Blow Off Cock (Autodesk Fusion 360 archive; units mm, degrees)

design "Blow Off Cock" references "Stud", "Gland", "Cock", "Body", "Nut"
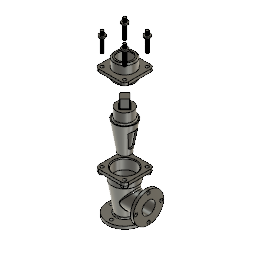
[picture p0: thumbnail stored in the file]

design "Nut"
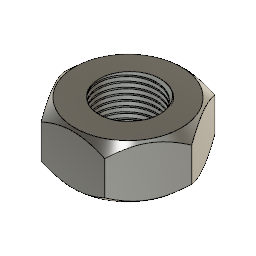
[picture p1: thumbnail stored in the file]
sketch "Sketch1" plane through (0, 0, 0) normal (0, 0, 1) x axis (1, 0, 0)
  line L1 (-12, 0) -> (-6, 10.3923)
  line L2 (-6, -10.3923) -> (-12, 0)
  line L3 (6, -10.3923) -> (-6, -10.3923)
  line L4 (12, 0) -> (6, -10.3923)
  line L5 (6, 10.3923) -> (12, 0)
  line L6 (-6, 10.3923) -> (6, 10.3923)
  circle C1 centre (0, 0) radius 6
  point P1 (0, 0)
  point P2 (0, 0)
  point P9 (0, 0)
  point P4 (-12, 0)
  point P7 (12, 0)
  point P3 (-6, 10.3923)
  point P8 (6, 10.3923)
  coincident P1 P2
  coincident P2 P9
  horizontal P4 P7
  dimension "d1" diameter C1 = 12
  dimension "d2" distance P3 P8 = 12
extrude "Extrude1" new body sketch "Sketch1" distance 10
sketch "Sketch2" plane through (0, 0, 5) normal (0, 0, 1) x axis (-1, 0, 0)
  line L1 (6, -10.3923) -> (-6, -10.3923)
  line L2 (12, 0) -> (6, -10.3923)
  line L3 (6, 10.3923) -> (12, 0)
  line L4 (-6, 10.3923) -> (6, 10.3923)
  line L5 (-12, 0) -> (-6, 10.3923)
  line L6 (-6, -10.3923) -> (-12, 0)
  circle C1 centre (0, 0) radius 6
  circle C2 centre (0, 0) radius 10
  point P1 (0, 0)
  point P9 (0, 0)
  coincident P1 P9
  dimension "d5" diameter C2 = 20
extrude "Extrude2" sketch "Sketch2" profile of C1 C2 no distance stored taper 48
mirror "Mirror1"
thread "Thread1"

design "Cock"
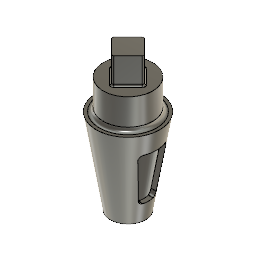
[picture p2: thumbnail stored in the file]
sketch "Sketch1" plane through (0, 0, 0) normal (0, 1, 0) x axis (1, 0, 0)
  line L1 (23, 0) -> (17, 0)
  line L2 (41, -110) -> (23, 0)
  line L3 (0, -144.3099) -> (0, 0)
  line L4 (17, 0) -> (34.0182, -104)
  line L5 (37.7698, 0) -> (0, 0)
  line L6 (32, -110) -> (41, -110)
  line L7 (32, -149) -> (32, -110)
  line L8 (26, -104) -> (34.0182, -104)
  line L9 (26, -143) -> (26, -104)
  line L10 (0, -149) -> (32, -149)
  line L11 (0, -143) -> (26, -143)
  line L12 (0, -143) -> (0, -149)
  point P1 (0, 0)
  point P4 (0, 0)
  point P8 (0, 0)
  point P7 (17, 0)
  point P14 (0, -149)
  point P15 (0, -143)
  point P3 (41, -110)
  horizontal L1
  coincident P1 P4
  perpendicular L1 L3
  parallel L2 L4
  coincident P1 P8
  perpendicular L3 L5
  horizontal P1 P7
  horizontal L6
  perpendicular L6 L7
  horizontal L8
  perpendicular L8 L9
  perpendicular L7 L10
  coincident L3 P14
  coincident L3 P15
  perpendicular L3 L11
  dimension "d1" = 46
  dimension "d2" = 34
  dimension "d3" distance L1 P3 = 110
  dimension "d4" = 82
  dimension "d5" distance L6 L8 = 6
  dimension "d7" = 64
  dimension "d8" distance L7 L9 = 6
  dimension "d9" distance L5 L10 = 149
  dimension "d10" distance L10 L11 = 6
revolve "Revolve1" sketch "Sketch1" AlongAngle 360
sketch "Sketch2" plane through (0, 0, 149) normal (0, 0, 1) x axis (-1, 0, 0)
  line L1 (21.2132, 0) -> (0, -21.2132)
  line L2 (0, 21.2132) -> (21.2132, 0)
  line L3 (-21.2132, 0) -> (0, 21.2132)
  line L4 (0, -21.2132) -> (-21.2132, 0)
  point P1 (0, 0)
  point P3 (21.2132, 0)
  point P5 (-21.2132, 0)
  point P2 (0, -21.2132)
  point P4 (0, 21.2132)
  perpendicular L2 L3
  horizontal P1 P3
  horizontal P1 P5
  vertical P1 P2
  vertical P1 P4
  equal L1 L2
  equal L1 L4
  dimension "d28" distance P2 P5 = 30
extrude "Extrude1" add sketch "Sketch2" along normal blind 34
fillet "Fillet1" radius 2
fillet "Fillet2" radius 2
fillet "Fillet3" radius 5
fillet "Fillet4" radius 5
sketch "Sketch5" plane through (0, 0, 0) normal (1, 0, 0) x axis (0, 1, 0)
  line L1 (-23, 0) -> (23, 0)
  line L2 (0, 97.021) -> (0, 0)
  line L3 (13.3134, 85) -> (-13.3134, 85)
  line L4 (11.5626, 27.3601) -> (18.2723, 79.3601)
  line L5 (-6.6037, 23) -> (6.6037, 23)
  line L6 (-18.2723, 79.3601) -> (-11.5626, 27.3601)
  line L7 (-41, 110) -> (41, 110)
  arc A1 centre (-13.3134, 80) radius 5 clockwise from (-18.2723, 79.3601) to (-13.3134, 85)
  arc A2 centre (13.3134, 80) radius 5 clockwise from (13.3134, 85) to (18.2723, 79.3601)
  arc A3 centre (6.6037, 28) radius 5 clockwise from (11.5626, 27.3601) to (6.6037, 23)
  arc A4 centre (-6.6037, 28) radius 5 clockwise from (-6.6037, 23) to (-11.5626, 27.3601)
  point P1 (0, 0)
  point P4 (0, 0)
  point P6 (-19, 85)
  point P7 (19, 85)
  point P8 (11, 23)
  point P9 (-11, 23)
  coincident P1 P4
  perpendicular L1 L2
  perpendicular L2 L3
  perpendicular L2 L5
  symmetric L2 P6 P7
  symmetric L2 P8 P9
  coincident P6 L6
  tangent L3 A1
  tangent L6 A1
  coincident P7 L4
  coincident P7 L3
  tangent L4 A2
  tangent L3 A2
  equal A1 A2
  coincident P8 L4
  tangent L4 A3
  tangent L5 A3
  equal A1 A3
  coincident P9 L5
  coincident P9 L6
  tangent L5 A4
  tangent L6 A4
  equal A1 A4
  dimension "d36" distance L3 L5 = 62
  dimension "d37" distance L3 L7 = 25
  dimension "d38" distance P6 P7 = 38
  dimension "d39" distance P8 P9 = 22
  dimension "d40" radius A1 = 5
extrude "Extrude4" cut sketch "Sketch5" profile of L3 L4 L5 L6 A1 A2 A3 A4 no distance stored
sketch "Sketch4" plane through (0, 0, 143) normal (0, 0, -1) x axis (1, 0, 0)
  circle C1 centre (0, 0) radius 26
  circle C2 centre (0, 0) radius 12
  point P1 (0, 0)
  point P3 (0, 0)
  coincident P1 P3
  dimension "d31" diameter C2 = 24
extrude "Extrude3" cut sketch "Sketch4" profile of C2 against normal blind 32
fillet "Fillet5" radius 5
fillet "Fillet6" radius 5

design "Gland"
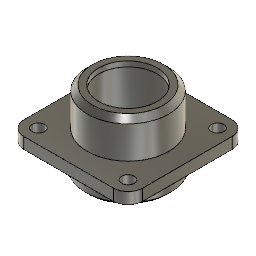
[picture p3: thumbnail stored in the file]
sketch "Sketch1" plane through (0, 0, 0) normal (0, 0, 1) x axis (1, 0, 0)
  circle C1 centre (0, 0) radius 41
  point P1 (0, 0)
  point P2 (0, 0)
  coincident P1 P2
  dimension "d1" diameter C1 = 82
extrude "Extrude1" new body sketch "Sketch1" along normal blind 25
sketch "Sketch2" plane through (0, 0, 25) normal (0, 0, 1) x axis (-1, 0, 0)
  line L1 (57, -57) -> (-57, -57)
  line L2 (57, 57) -> (57, -57)
  line L3 (-57, 57) -> (57, 57)
  line L4 (-57, -57) -> (-57, 57)
  line L5 (57, 57) -> (-57, -57)
  line L6 (-57, 57) -> (57, -57)
  circle C1 centre (0, 0) radius 41
  point P7 (0, 0)
  point P1 (0, 0)
  point P3 (-57, -57)
  point P4 (57, -57)
  point P5 (57, 57)
  horizontal L1
  perpendicular L1 L2
  parallel L1 L3
  parallel L2 L4
  coincident L5 P7
  coincident L6 P7
  coincident P1 P7
  dimension "d4" distance P3 P4 = 114
  dimension "d5" distance P4 P5 = 114
extrude "Extrude2" add sketch "Sketch2" profile of C1 L1 L2 L3 L4 along normal blind 11
fillet "Fillet1" sketch "Sketch5" radius 14
sketch "Sketch3" plane through (0, 0, 36) normal (0, 0, 1) x axis (-1, 0, 0)
  line L1 (43, -57) -> (-43, -57)
  line L2 (57, 43) -> (57, -43)
  line L3 (-43, 57) -> (43, 57)
  line L4 (-57, -43) -> (-57, 43)
  arc A1 centre (-43, -43) radius 14 clockwise from (-43, -57) to (-57, -43)
  arc A2 centre (43, -43) radius 14 clockwise from (57, -43) to (43, -57)
  arc A3 centre (43, 43) radius 14 clockwise from (43, 57) to (57, 43)
  arc A4 centre (-43, 43) radius 14 clockwise from (-57, 43) to (-43, 57)
  circle C1 centre (0, 0) radius 39
  point P1 (0, 0)
  point P14 (0, 0)
  coincident P1 P14
  dimension "d9" diameter C1 = 78
extrude "Extrude3" add sketch "Sketch3" profile of C1 along normal blind 36
chamfer "Chamfer1" distance 5 rotateAngle 45
sketch "Sketch4" plane through (0, 0, 0) normal (0, 1, 0) x axis (1, 0, 0)
  line L1 (-34, -72) -> (34, -72)
  line L2 (0, -90.6958) -> (0, 0)
  line L3 (-28, -72) -> (0, -72)
  line L4 (-28, -67) -> (-28, -72)
  line L5 (39, -67) -> (-39, -67)
  line L6 (-34, -67) -> (-28, -67)
  line L7 (-34, -21) -> (-34, -67)
  line L8 (-32, -21) -> (-34, -21)
  line L9 (41, 0) -> (-41, 0)
  line L10 (-32, 0) -> (-32, -21)
  line L11 (0, 0) -> (-32, 0)
  line L12 (0, -72) -> (0, 0)
  point P1 (0, 0)
  point P4 (0, 0)
  point P6 (0, -72)
  point P11 (-34, -67)
  point P16 (-32, 0)
  point P7 (-28, -72)
  point P17 (0, 0)
  point P18 (0, 0)
  point P8 (-28, -67)
  point P13 (-32, -21)
  coincident P1 P4
  perpendicular L1 L2
  coincident L2 P6
  perpendicular L2 L3
  perpendicular L3 L4
  coincident L5 P11
  perpendicular L4 L6
  perpendicular L5 L7
  perpendicular L7 L8
  coincident L9 P16
  perpendicular L5 L10
  coincident L1 P7
  coincident P1 P17
  coincident P1 P18
  dimension "d15" distance L2 L4 = 28
  dimension "d16" distance L1 P8 = 5
  dimension "d17" distance L2 L7 = 34
  dimension "d18" distance L2 L10 = 32
  dimension "d19" distance P13 P16 = 21
revolve "Revolve1" sketch "Sketch4" AlongAngle 360
sketch "Sketch5" plane through (0, 0, 36) normal (0, 0, 1) x axis (-1, 0, 0)
  line L1 (43, -57) -> (-43, -57)
  line L2 (57, 43) -> (57, -43)
  line L3 (-43, 57) -> (43, 57)
  line L4 (-57, -43) -> (-57, 43)
  circle C1 centre (0, 0) radius 39
  arc A1 centre (-43, -43) radius 14 clockwise from (-43, -57) to (-57, -43)
  arc A2 centre (43, -43) radius 14 clockwise from (57, -43) to (43, -57)
  arc A3 centre (43, 43) radius 14 clockwise from (43, 57) to (57, 43)
  arc A4 centre (-43, 43) radius 14 clockwise from (-57, 43) to (-43, 57)
  circle C2 centre (43, 43) radius 6
  concentric A3 C2
  dimension "d26" diameter C2 = 12
extrude "Extrude4" cut sketch "Sketch5" profile of C2 to an object
rectangular_pattern "R-Pattern1" uSpaceDistance 86 vSpaceDistance 86
chamfer "Chamfer2" distance 3 rotateAngle 45

design "Stud"
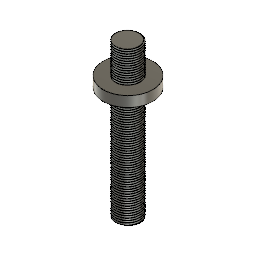
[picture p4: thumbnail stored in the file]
sketch "Sketch1" plane through (0, 0, 0) normal (0, 0, 1) x axis (1, 0, 0)
  circle C1 centre (0, 0) radius 6
  point P1 (0, 0)
  point P2 (0, 0)
  coincident P1 P2
  dimension "d1" diameter C1 = 12
extrude "Extrude1" new body sketch "Sketch1" along normal blind 54
sketch "Sketch2" plane through (0, 0, 54) normal (0, 0, 1) x axis (-1, 0, 0)
  circle C1 centre (0, 0) radius 6
  circle C2 centre (0, 0) radius 12
  point P1 (0, 0)
  point P3 (0, 0)
  coincident P1 P3
  dimension "d4" diameter C2 = 24
extrude "Extrude2" add sketch "Sketch2" along normal blind 5
sketch "Sketch3" plane through (0, 0, 59) normal (0, 0, 1) x axis (-1, 0, 0)
  circle C1 centre (0, 0) radius 12
  circle C2 centre (0, 0) radius 6
  point P1 (0, 0)
  point P3 (0, 0)
  coincident P1 P3
  dimension "d7" diameter C2 = 12
extrude "Extrude3" add sketch "Sketch3" profile of C2 along normal blind 15
thread "Thread1"
thread "Thread2"

design "Body"
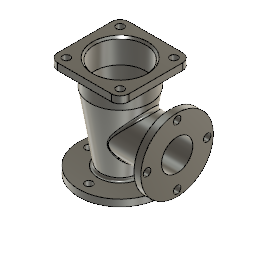
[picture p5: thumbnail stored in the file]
sketch "Sketch1" plane through (0, 0, 0) normal (0, 1, 0) x axis (1, 0, 0)
  line L1 (0, -187.0761) -> (0, 0)
  line L2 (30, -22) -> (30, 0)
  line L3 (17.5, 0) -> (30, 0)
  line L4 (17.5, -33) -> (17.5, 0)
  line L5 (66, -22) -> (30, -22)
  line L6 (66, -33) -> (66, -22)
  line L7 (30, -33) -> (66, -33)
  line L8 (48, -143) -> (30, -33)
  line L9 (48, -171) -> (48, -143)
  line L10 (41, -171) -> (48, -171)
  line L11 (41, -143) -> (41, -171)
  line L12 (23, -33) -> (41, -143)
  line L13 (23, -33) -> (17.5, -33)
  point P1 (0, 0)
  point P2 (0, 0)
  point P4 (30, 0)
  point P15 (23, -33)
  point P16 (23, -33)
  point P5 (30, -22)
  point P11 (48, -143)
  point P12 (48, -171)
  point P6 (17.5, 0)
  point P7 (17.5, -33)
  coincident P1 P2
  vertical L1
  parallel L1 L2
  horizontal P1 P4
  perpendicular L2 L3
  perpendicular L3 L4
  perpendicular L2 L5
  perpendicular L5 L6
  perpendicular L6 L7
  vertical L9
  perpendicular L9 L10
  perpendicular L10 L11
  equal L9 L11
  parallel L8 L12
  perpendicular L4 L13
  coincident P15 P16
  dimension "d1" = 60
  dimension "d2" = 35
  dimension "d3" distance P4 P5 = 22
  dimension "d5" = 132
  dimension "d7" = 60
  dimension "d8" = 96
  dimension "d9" distance L7 P11 = 110
  dimension "d10" distance P11 P12 = 28
  dimension "d11" = 82
  dimension "d12" distance L3 L7 = 33
  dimension "d13" distance P6 P7 = 33
revolve "Revolve1" sketch "Sketch1" AlongAngle 360
work_plane "WorkPlane1" AlongDistance 80
sketch "Sketch2" plane through (80, 0, 0) normal (1, 0, 0) x axis (0, 1, 0)
  circle C1 centre (0, 93) radius 36
  point P1 (0, 0)
  point P2 (0, 93)
  vertical P1 P2
  dimension "d16" diameter C1 = 72
  dimension "d17" distance P1 P2 = 93
extrude "Extrude1" add sketch "Sketch2" to an object
sketch "Sketch3" plane through (80, 0, 0) normal (1, 0, 0) x axis (0, 1, 0)
  circle C1 centre (0, 93) radius 36
  circle C2 centre (0, 93) radius 25
  concentric C1 C2
  dimension "d24" diameter C2 = 50
extrude "Extrude2" cut sketch "Sketch3" profile of C2 to an object
sketch "Sketch4" plane through (80, 0, 0) normal (1, 0, 0) x axis (0, 1, 0)
  circle C1 centre (0, 93) radius 25
  circle C2 centre (0, 93) radius 36
  circle C3 centre (0, 93) radius 25
  circle C4 centre (0, 93) radius 58
  concentric C1 C3
  concentric C1 C4
  equal C1 C3
  dimension "d25" diameter C4 = 116
extrude "Extrude3" add sketch "Sketch4" along normal blind 11
sketch "Sketch5" plane through (0, 0, 171) normal (0, 0, 1) x axis (-1, 0, 0)
  line L1 (57, -57) -> (-57, -57)
  line L2 (57, 57) -> (57, -57)
  line L3 (-57, 57) -> (57, 57)
  line L4 (-57, -57) -> (-57, 57)
  line L5 (57, 57) -> (-57, -57)
  line L6 (-57, 57) -> (57, -57)
  circle C1 centre (0, 0) radius 48
  circle C2 centre (0, 0) radius 41
  circle C3 centre (0, 0) radius 41
  point P7 (0, 0)
  point P1 (0, 0)
  point P8 (0, 0)
  point P4 (57, -57)
  point P5 (57, 57)
  point P3 (-57, -57)
  horizontal L1
  perpendicular L1 L2
  parallel L1 L3
  parallel L2 L4
  coincident L5 P7
  coincident L6 P7
  coincident P1 P7
  coincident P7 P8
  equal C2 C3
  dimension "d28" distance P4 P5 = 114
  dimension "d29" distance P3 P4 = 114
extrude "Extrude4" add sketch "Sketch5" profile of C1 C2 L1 L2 L3 L4 C3 along normal blind 11
fillet "Fillet1" radius 14
sketch "Sketch6" plane through (0, 0, 182) normal (0, 0, 1) x axis (-1, 0, 0)
  line L1 (43, -57) -> (-43, -57)
  line L2 (57, 43) -> (57, -43)
  line L3 (-43, 57) -> (43, 57)
  line L4 (-57, -43) -> (-57, 43)
  arc A1 centre (-43, -43) radius 14 clockwise from (-43, -57) to (-57, -43)
  arc A2 centre (43, -43) radius 14 clockwise from (57, -43) to (43, -57)
  arc A3 centre (43, 43) radius 14 clockwise from (43, 57) to (57, 43)
  arc A4 centre (-43, 43) radius 14 clockwise from (-57, 43) to (-43, 57)
  circle C1 centre (0, 0) radius 41
  circle C2 centre (43, 43) radius 6
  circle C3 centre (43, -43) radius 6
  circle C4 centre (-43, -43) radius 6
  circle C5 centre (-43, 43) radius 6
  concentric A3 C2
  concentric A2 C3
  concentric A1 C4
  concentric A4 C5
  equal C2 C3
  equal C3 C4
  equal C4 C5
  dimension "d33" diameter C2 = 12
extrude "Extrude5" cut sketch "Sketch6" profile of C2 C3 C4 C5 to an object
sketch "Sketch7" plane through (0, 0, 33) normal (0, 0, 1) x axis (-1, 0, 0)
  circle C1 centre (0, 0) radius 66
  circle C2 centre (0, 0) radius 30
  circle C3 centre (0, 50) radius 6
  point P1 (0, 0)
  point P3 (0, 50)
  vertical P1 P3
  dimension "d38" diameter C3 = 12
  dimension "d39" distance P1 P3 = 50
extrude "Extrude6" cut sketch "Sketch7" profile of C3 to an object
circular_pattern "C-Pattern1" TotalAngle 360
fillet "Fillet2" radius 4
chamfer "Chamfer1" distance 3 rotateAngle 45
sketch "Sketch9" plane through (91, 0, 0) normal (1, 0, 0) x axis (0, 1, 0)
  line L1 (-65.6451, 93) -> (0, 93)
  circle C1 centre (0, 93) radius 25
  circle C2 centre (0, 93) radius 58
  circle C3 centre (-48, 93) radius 6
  point P2 (0, 93)
  point P4 (0, 93)
  point P3 (-48, 93)
  coincident P2 P4
  horizontal L1
  coincident P3 L1
  dimension "d48" diameter C3 = 12
  dimension "d49" distance P3 P4 = 48
extrude "Extrude7" cut sketch "Sketch9" profile of C3 to an object
circular_pattern "C-Pattern2" TotalAngle 360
